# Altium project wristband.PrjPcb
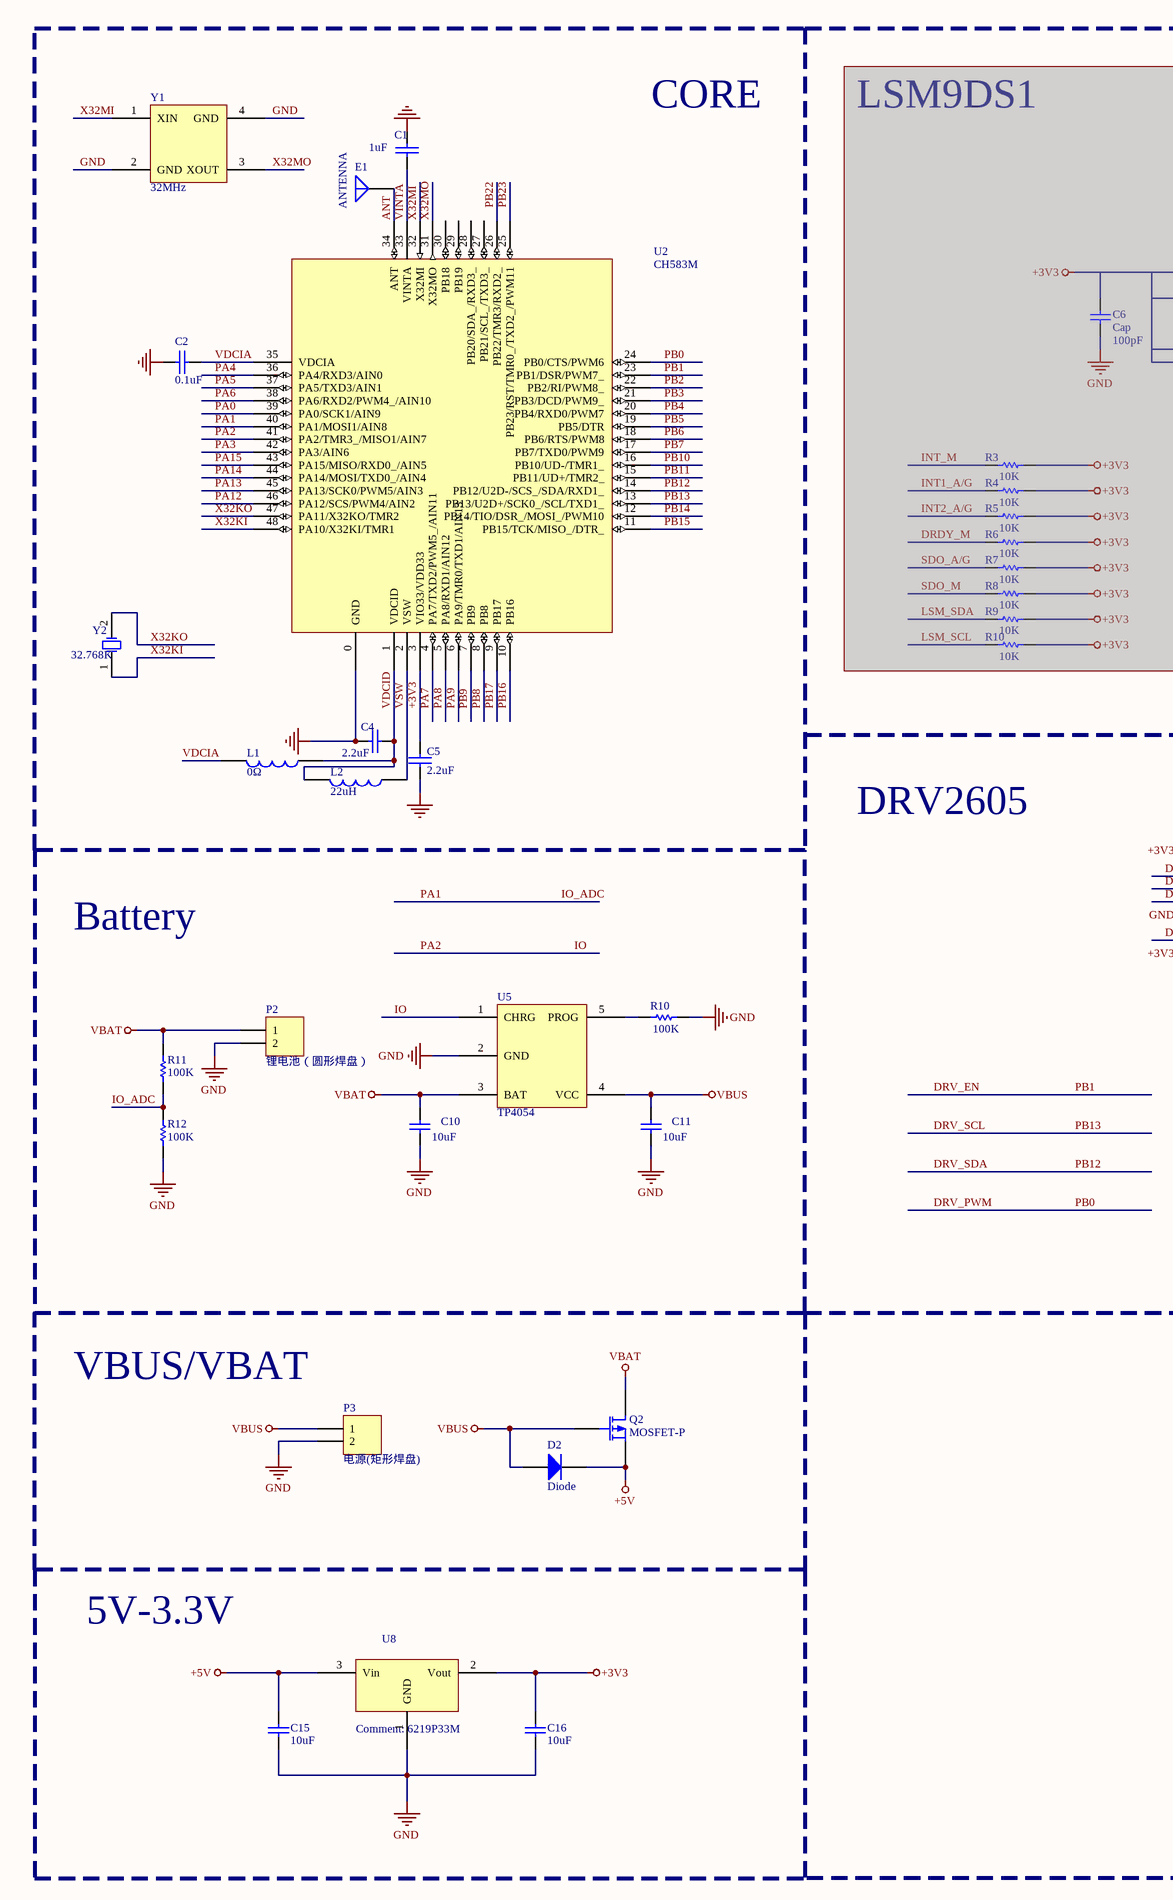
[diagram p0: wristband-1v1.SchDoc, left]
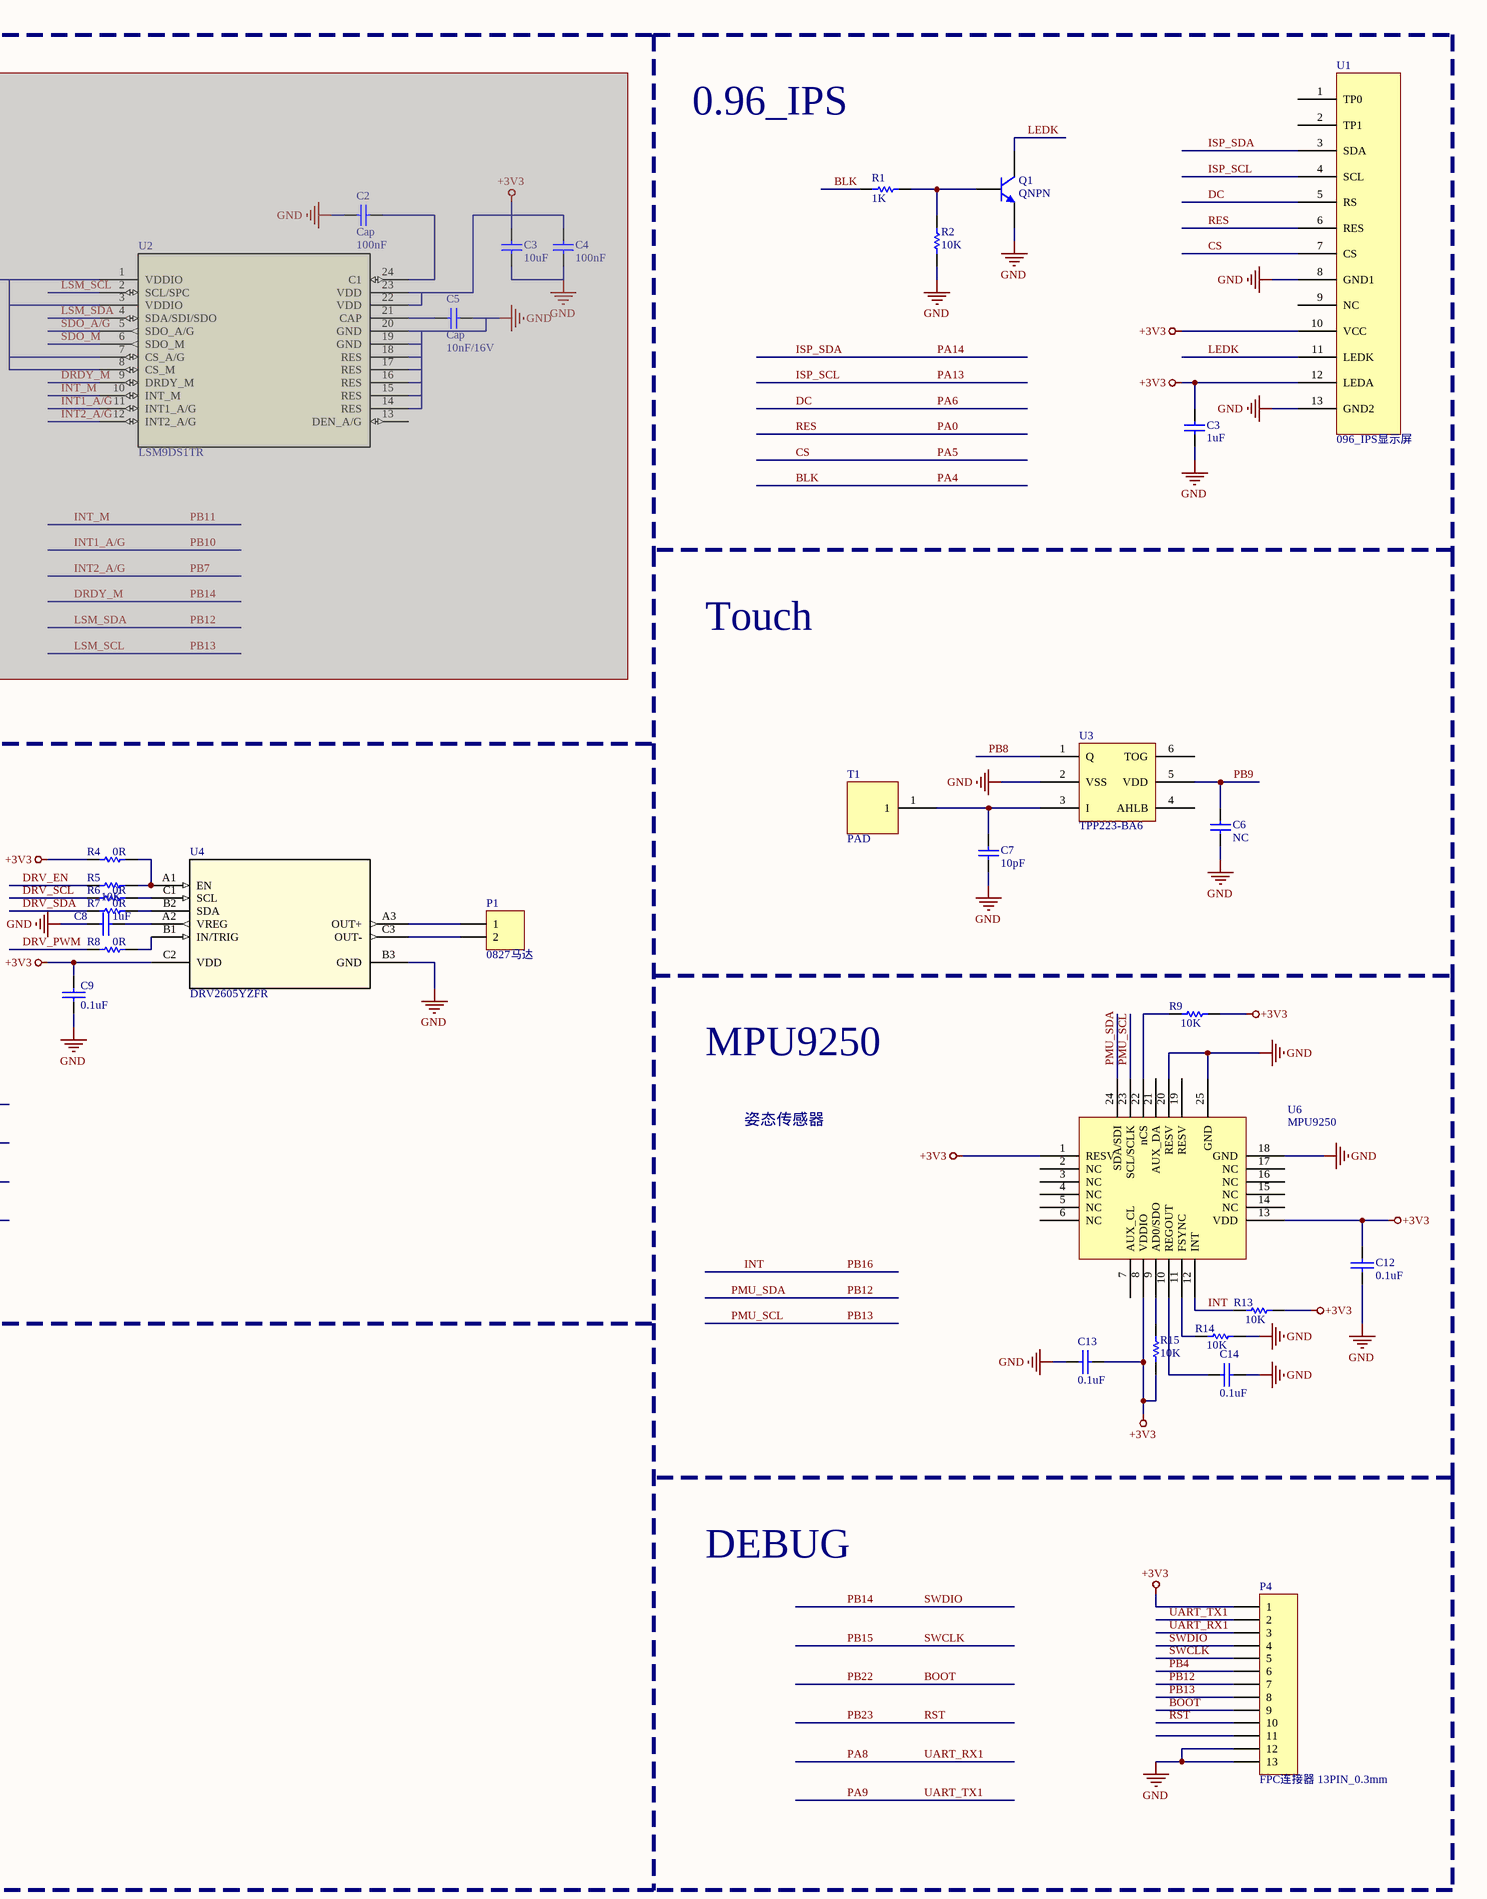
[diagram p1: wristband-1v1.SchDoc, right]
1 sheet, 64 parts. Net scope: global (net labels, ports and power ports of the same name join across sheets).
Board file: wristband-1v1.PcbDoc

## Sheet wristband-1v1.SchDoc
size A2

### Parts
(Parts that share a designator on the sheet are numbered #1, #2 ... from top to bottom, then left to right.)
C1  1uF  [0402_C]
C2#1  Cap  value 100nF  [RAD-0.3]  (masked out: inside a compile mask, not in the netlist)
C2#2  0.1uF  [0402_C]
C3#1  10uF  [RAD-0.3]  (masked out: inside a compile mask, not in the netlist)
C3#2  1uF  [0402_C]
C4#1  100nF  [RAD-0.3]  (masked out: inside a compile mask, not in the netlist)
C4#2  2.2uF  [0402_C]
C5#1  Cap  value 10nF/16V  [RAD-0.3]  (masked out: inside a compile mask, not in the netlist)
C5#2  2.2uF  [0402_C]
C6#1  Cap  value 100pF  [RAD-0.3]  (masked out: inside a compile mask, not in the netlist)
C6#2  NC  [0402_C]
C7  10pF  [0402_C]
C8  1uF  [0402_C]
C9  0.1uF  [0402_C]
C10  10uF  [0603_C]
C11  10uF  [0603_C]
C12  0.1uF  [0402_C]
C13  0.1uF  [0402_C]
C14  0.1uF  [0402_C]
C15  10uF  [0603_C]
C16  10uF  [0603_C]
D2  Diode  [SOD-323]
E1  ANTENNA  [ANT-F-1-2.4G-0.8]
L1  0Ω  [0603]
L2  22uH  [SMD_2x2mm]
P1  0827马达  [SIP2-2.54mm]
P2  锂电池（圆形焊盘）  [SIP2-2.54mm]
P3  电源(矩形焊盘)  [SIP2-2.54mm]
P4  FPC连接器 13PIN_0.3mm  [FFC/FPC-13(6+7)-P0.3]
Q1  QNPN  [SOT-23]
Q2  MOSFET-P  [SOT-23]
R1  1K  [0402]
R2  10K  [0402]
R3  10K  [AXIAL-0.3]  (masked out: inside a compile mask, not in the netlist)
R4#1  10K  [AXIAL-0.3]  (masked out: inside a compile mask, not in the netlist)
R4#2  0R  [0402]
R5#1  10K  [AXIAL-0.3]  (masked out: inside a compile mask, not in the netlist)
R5#2  10K  [0402]
R6#1  10K  [AXIAL-0.3]  (masked out: inside a compile mask, not in the netlist)
R6#2  0R  [0402]
R7#1  10K  [AXIAL-0.3]  (masked out: inside a compile mask, not in the netlist)
R7#2  0R  [0402]
R8#1  10K  [AXIAL-0.3]  (masked out: inside a compile mask, not in the netlist)
R8#2  0R  [0402]
R9#1  10K  [AXIAL-0.3]  (masked out: inside a compile mask, not in the netlist)
R9#2  10K  [0402]
R10#1  10K  [AXIAL-0.3]  (masked out: inside a compile mask, not in the netlist)
R10#2  100K  [0402]
R11  100K  [0402]
R12  100K  [0402]
R13  10K  [0402]
R14  10K  [0402]
R15  10K  [0402]
T1  PAD  [TESTPOINT1]
U1  096_IPS显示屏  [FFC-13-P0.7]
U2#1  CH583M  [QFN48_5X5]
U2#2  LSM9DS1TR  [LGA-24_3X3P5X1_STM]  (masked out: inside a compile mask, not in the netlist)
U3  TPP223-BA6  [SOT-23-6]
U4  DRV2605YZFR  [DSBGA-9-P0.5-H0.625mm]
U5  TP4054  [SOT-23-5]
U6  MPU9250  [QFN24-3.0X3.0X1.0]
U8  6219P33M  [SOT-23]
Y1  32MHz  [XT2016]
Y2  32.768K  [fc-135]

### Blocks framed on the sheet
CORE: C1 C2#2 C4#2 C5#2 E1 L1 L2 U2#1 Y1 Y2

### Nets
+3V3: C3#2.1 C5#2.2 C9.2 C12.2 C13.2 C16.1 P4.1 R4#2.1 R9#2.2 R13.2 R15.2 U1.10(VCC) U1.12(LEDA) U2#1.3(VIO33/VDD33) U4.C2(VDD) U6.1(RESV) U6.8(VDDIO) U6.13(VDD) U8.2(Vout)
+5V: C15.1 D2.2(K) Q2.2(S) U8.3(Vin)
GND: C1.2 C2#2.2 C3#2.2 C4#2.1 C5#2.1 C6#2.2 C7.2 C8.1 C9.1 C10.1 C11.1 C12.1 C13.1 C14.2 C15.2 C16.2 P2.2 P3.2 P4.12 P4.13 Q1.2(E) R2.2 R10#2.2 R12.1 R14.2 U1.8(GND1) U1.13(GND2) U2#1.0(GND) U3.2(VSS) U4.B3(GND) U5.2(GND) U6.18(GND) U6.20(RESV) U6.25(GND) U8.1(GND) Y1.2(GND) Y1.4(GND)
VBAT: C10.2 P2.1 Q2.3(D) R11.1 U5.3(BAT)
VBUS: C11.2 D2.1(A) P3.1 Q2.1(G) U5.4(VCC)
ANT: E1.1(A) U2#1.34(ANT)
BLK: R1.2 U2#1.36(PA4/RXD3/AIN0)  [also labelled PA4]
BOOT: P4.9 U2#1.26(PB22/TMR3/RXD2_)  [also labelled PB22]
CS: U1.7(CS) U2#1.37(PA5/TXD3/AIN1)  [also labelled PA5]
DC: U1.5(RS) U2#1.38(PA6/RXD2/PWM4_/AIN10)  [also labelled PA6]
DRV_EN: R5#2.1 U2#1.23(PB1/DSR/PWM7_)  [also labelled PB1]
DRV_PWM: R8#2.1 U2#1.24(PB0/CTS/PWM6)  [also labelled PB0]
DRV_SCL: P4.8 R6#2.1 U2#1.13(PB13/U2D+/SCK0_/SCL/TXD1_) U6.23(SCL/SCLK)  [also labelled PB13, PMU_SCL]
DRV_SDA: P4.7 R7#2.1 U2#1.14(PB12/U2D-/SCS_/SDA/RXD1_) U6.24(SDA/SDI)  [also labelled PB12, PMU_SDA]
INT: R13.1 U2#1.10(PB16) U6.12(INT)  [also labelled PB16]
IO: U2#1.41(PA2/TMR3_/MISO1/AIN7) U5.1(CHRG)  [also labelled PA2]
IO_ADC: R11.2 R12.2 U2#1.40(PA1/MOSI1/AIN8)  [also labelled PA1]
ISP_SCL: U1.4(SCL) U2#1.45(PA13/SCK0/PWM5/AIN3)  [also labelled PA13]
ISP_SDA: U1.3(SDA) U2#1.44(PA14/MOSI/TXD0_/AIN4)  [also labelled PA14]
LEDK: Q1.3(C) U1.11(LEDK)
PA0: U1.6(RES) U2#1.39(PA0/SCK1/AIN9)  [also labelled RES]
PA3: U2#1.42(PA3/AIN6)
PA7: U2#1.4(PA7/TXD2/PWM5_/AIN11)
PA8: P4.3 U2#1.5(PA8/RXD1/AIN12)  [also labelled UART_RX1]
PA9: P4.2 U2#1.6(PA9/TMR0/TXD1/AIN13)  [also labelled UART_TX1]
PA12: U2#1.46(PA12/SCS/PWM4/AIN2)
PA15: U2#1.43(PA15/MISO/RXD0_/AIN5)
PB2: U2#1.22(PB2/RI/PWM8_)
PB3: U2#1.21(PB3/DCD/PWM9_)
PB4: P4.6 U2#1.20(PB4/RXD0/PWM7)
PB5: U2#1.19(PB5/DTR)
PB6: U2#1.18(PB6/RTS/PWM8)
PB7: U2#1.17(PB7/TXD0/PWM9)
PB8: U2#1.8(PB8) U3.1(Q)
PB9: C6#2.1 U2#1.7(PB9) U3.5(VDD)
PB10: U2#1.16(PB10/UD-/TMR1_)
PB11: U2#1.15(PB11/UD+/TMR2_)
PB14: P4.4 U2#1.12(PB14/TIO/DSR_/MOSI_/PWM10)  [also labelled SWDIO]
PB15: P4.5 U2#1.11(PB15/TCK/MISO_/DTR_)  [also labelled SWCLK]
PB17: U2#1.9(PB17)
PB23: P4.10 U2#1.25(PB23/RST/TMR0_/TXD2_/PWM11)  [also labelled RST]
VDCIA: C2#2.1 L1.2 U2#1.35(VDCIA)
VDCID: C4#2.2 L1.1 L2.2 U2#1.1(VDCID)
VINTA: C1.1 U2#1.33(VINTA)
VSW: L2.1 U2#1.2(VSW)
X32KI: U2#1.48(PA10/X32KI/TMR1) Y2.1(OSC1)
X32KO: U2#1.47(PA11/X32KO/TMR2) Y2.2(OSC2)
X32MI: U2#1.32(X32MI) Y1.1(XIN)
X32MO: U2#1.31(X32MO) Y1.3(XOUT)
NetC7_1: C7.1 T1.1 U3.3(I)
NetC8_2: C8.2 U4.A2(VREG)
NetC14_1: C14.1 U6.10(REGOUT)
NetP1_1: P1.1 U4.A3(OUT+)
NetP1_2: P1.2 U4.C3(OUT-)
NetQ1_1: Q1.1(B) R1.1 R2.1
NetR4#2_2: R4#2.2 R5#2.2 U4.A1(EN)
NetR6#2_2: R6#2.2 U4.C1(SCL)
NetR7#2_2: R7#2.2 U4.B2(SDA)
NetR8#2_2: R8#2.2 U4.B1(IN/TRIG)
NetR9#2_1: R9#2.1 U6.22(nCS)
NetR10#2_1: R10#2.1 U5.5(PROG)
NetR14_1: R14.1 U6.11(FSYNC)
NetR15_1: R15.1 U6.9(AD0/SDO)

Not connected (* = marked no-connect by the designer): P4 11; U1 1(TP0) 2(TP1) 9(NC); U2#1 27(PB21/SCL_/TXD3_) 28(PB20/SDA_/RXD3_) 29(PB19) 30(PB18); U3 4(AHLB) 6(TOG); U6 2(NC) 3(NC) 4(NC) 5(NC) 6(NC) 7(AUX_CL) 14(NC) 15(NC) 16(NC) 17(NC) 19(RESV) 21(AUX_DA)

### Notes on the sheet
- LSM9DS1
- 0.96_IPS
- Touch
- DRV2605
- Battery
- MPU9250
- 姿态传感器
- VBUS/VBAT
- DEBUG
- 5V-3.3V

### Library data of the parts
C1 C2#2 C4#2 C5#2 C8 C9 C12-C14 = CAP: Capacitor
C2#1 C3#1 C3#2 C4#1 C5#1 C6#1 C6#2 C7 C10 C11 C15 C16 = Cap: Capacitor
D2 = Diode: Default Diode
E1 = ANTENNA: Generic Antenna
L1 L2 = INDUCTOR
P1 = Header 2H: Header, 2-Pin, Right Angle
P2 P3 = Header 2: Header, 2-Pin
P4 = Header 13: Header, 13-Pin
Q1 = QNPN: NPN Bipolar Transistor
Q2 = MOSFET-P: P-Channel MOSFET
R1-R3 R4#1 R4#2 R5#1 R5#2 R6#1 R6#2 R7#1 R7#2 R8#1 R8#2 R9#1 R9#2 R10#1 R10#2 R11-R15 = Res1: Resistor
U1 = Component_1
U2#1 = CH583M: RISC-V MCU with BLE/2*USB/ADC/PWM/SPI/I2C/4*UART
U2#2 = LSM9DS1TR: No Description Available; Vendor: STMicroelectronics; Built_By: EMA_Jessica; SourceLibrary: Updates_to_database_2020-11-03
U4 = DRV2605YZFR: No Description Available; Vendor: TEXAS INSTRUMENTS
U6 = PMU9250
Y1 = 晶体
Y2 = XTAL: Crystal Oscillator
